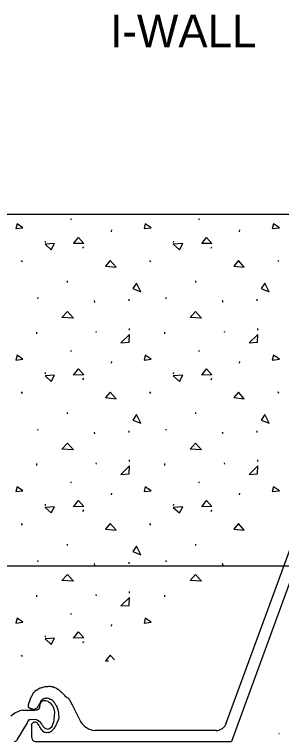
# Model space of a CAD drawing. Extents: x 22369.6 to 22384.3, y 22369.6 to 22381.8.
# Drawn here: x 22371.507 to 22371.886, y 22378.862 to 22379.896 of the extents above; entities that cross this region are included whole.
import ezdxf

# ---------------------------------------------------------------- set-up
doc = ezdxf.new("R2010")
doc.units = 0
for name, color, linetype in [('Level 1', 7, 'Continuous'), ('Level 10', 7, 'Continuous'), ('Level 4', 7, 'Continuous'), ('Level 8', 7, 'Continuous')]:
    doc.layers.add(name, color=color, linetype=linetype)

msp = doc.modelspace()

# ---------------------------------------------------------------- linework, layer by layer
at = {"layer": 'Level 1'}
for p, q in [((22371.8077, 22378.8878), (22371.9809, 22379.3614)), ((22371.9881, 22379.3356), (22371.8149, 22378.8619)), ((22370.8029, 22379.1117), (22371.5521, 22379.1117)), ((22371.5521, 22379.1117), (22372.3014, 22379.1117)), ((22371.5887, 22378.9141), (22371.6005, 22378.8901)), ((22371.5179, 22378.9064), (22371.5354, 22378.9063)), ((22371.5106, 22378.8641), (22371.5249, 22378.8885)), ((22371.5312, 22378.867), (22371.5312, 22378.8838)), ((22371.7931, 22378.8775), (22371.6207, 22378.8775)), ((22371.5358, 22378.8619), (22371.8149, 22378.8619))]:
    msp.add_line(p, q, dxfattribs=at)
for points in [[(22371.5388, 22378.9097), (22371.5384, 22378.9092), (22371.5374, 22378.9086), (22371.5371, 22378.9086), (22371.5363, 22378.9078), (22371.5356, 22378.9076), (22371.5354, 22378.9074), (22371.5342, 22378.9074), (22371.5338, 22378.9074), (22371.5332, 22378.9075), (22371.5329, 22378.9075), (22371.5323, 22378.9076), (22371.5319, 22378.9076), (22371.5316, 22378.9077), (22371.5313, 22378.9077), (22371.5306, 22378.9081), (22371.5298, 22378.9082), (22371.5294, 22378.9084), (22371.5291, 22378.9086), (22371.5288, 22378.9089), (22371.5276, 22378.9096), (22371.5272, 22378.9098), (22371.5271, 22378.9101), (22371.5267, 22378.9104), (22371.5265, 22378.9109), (22371.5264, 22378.912), (22371.5266, 22378.9132), (22371.5266, 22378.9144), (22371.5268, 22378.9149), (22371.5269, 22378.9155), (22371.5271, 22378.916), (22371.5271, 22378.9167), (22371.5282, 22378.9187), (22371.5286, 22378.9199), (22371.5286, 22378.9202), (22371.5288, 22378.9209), (22371.5289, 22378.9212), (22371.5295, 22378.9227), (22371.5299, 22378.9239), (22371.5304, 22378.9254), (22371.5307, 22378.9257), (22371.5312, 22378.9262), (22371.5319, 22378.9276), (22371.5322, 22378.9283), (22371.5326, 22378.9293), (22371.533, 22378.9301), (22371.5332, 22378.9303), (22371.5334, 22378.9308), (22371.5336, 22378.9311), (22371.5342, 22378.9316), (22371.535, 22378.9322), (22371.5352, 22378.9325), (22371.5357, 22378.9328), (22371.5359, 22378.9331), (22371.5361, 22378.9333), (22371.5366, 22378.9341), (22371.5374, 22378.9346), (22371.5382, 22378.935), (22371.5384, 22378.9353), (22371.5406, 22378.9369), (22371.542, 22378.9375), (22371.5426, 22378.9378), (22371.5433, 22378.938), (22371.5439, 22378.9382), (22371.5456, 22378.9385), (22371.5463, 22378.9386), (22371.5471, 22378.9389), (22371.5481, 22378.9394), (22371.549, 22378.9395), (22371.5501, 22378.9399), (22371.551, 22378.9399), (22371.5544, 22378.9401), (22371.5553, 22378.9404), (22371.5565, 22378.9405), (22371.5573, 22378.9404), (22371.5583, 22378.9401), (22371.5598, 22378.9401), (22371.5605, 22378.9399), (22371.5615, 22378.9393), (22371.5622, 22378.9391), (22371.563, 22378.9389), (22371.5633, 22378.9386), (22371.5655, 22378.938), (22371.566, 22378.9378), (22371.5669, 22378.9374), (22371.5683, 22378.9363)], [(22371.5683, 22378.9363), (22371.5693, 22378.9356), (22371.5701, 22378.935), (22371.5705, 22378.9344), (22371.5715, 22378.9336), (22371.5721, 22378.9329), (22371.5726, 22378.9326), (22371.5728, 22378.9325), (22371.5736, 22378.932), (22371.574, 22378.9315), (22371.5741, 22378.9312), (22371.5748, 22378.9305), (22371.5752, 22378.9299), (22371.577, 22378.9282), (22371.5771, 22378.9276), (22371.578, 22378.9271), (22371.5783, 22378.9267), (22371.5799, 22378.9253), (22371.5811, 22378.9246), (22371.5824, 22378.9239), (22371.5827, 22378.9237), (22371.5831, 22378.9232), (22371.5836, 22378.9229), (22371.5842, 22378.922), (22371.5843, 22378.9217), (22371.5844, 22378.9215), (22371.5846, 22378.9211), (22371.5846, 22378.9212), (22371.5847, 22378.9212), (22371.5887, 22378.9141)], [(22371.5249, 22378.8885), (22371.5256, 22378.8904), (22371.5254, 22378.8904), (22371.5281, 22378.8929), (22371.5294, 22378.8933), (22371.5352, 22378.8935), (22371.538, 22378.893), (22371.5415, 22378.8908), (22371.545, 22378.8871), (22371.5461, 22378.8851), (22371.5466, 22378.8846), (22371.547, 22378.8836), (22371.5493, 22378.8814), (22371.551, 22378.8803), (22371.5536, 22378.8794), (22371.5563, 22378.8802), (22371.5601, 22378.883), (22371.5612, 22378.8863), (22371.5624, 22378.8899), (22371.5632, 22378.8928), (22371.5641, 22378.9041), (22371.5639, 22378.9039), (22371.5636, 22378.9061), (22371.5629, 22378.9077), (22371.5621, 22378.9107), (22371.561, 22378.9124), (22371.5589, 22378.9154), (22371.556, 22378.9175), (22371.5545, 22378.9185), (22371.551, 22378.9197), (22371.5505, 22378.9195), (22371.5503, 22378.9198), (22371.5489, 22378.9195), (22371.548, 22378.9196), (22371.5456, 22378.9187), (22371.5448, 22378.9185), (22371.5448, 22378.9182), (22371.5435, 22378.9169), (22371.5426, 22378.9146), (22371.5424, 22378.9111), (22371.5423, 22378.9103), (22371.5411, 22378.9076), (22371.5384, 22378.9062), (22371.5383, 22378.9066), (22371.5383, 22378.9064), (22371.5354, 22378.9063)], [(22371.5693, 22378.8929), (22371.5695, 22378.8933), (22371.57, 22378.8956), (22371.57, 22378.896), (22371.57, 22378.8964), (22371.5701, 22378.8971), (22371.5701, 22378.8979), (22371.5697, 22378.8995), (22371.5696, 22378.9001), (22371.5696, 22378.9002), (22371.5697, 22378.9006), (22371.5696, 22378.9007), (22371.5697, 22378.9012), (22371.5696, 22378.9017), (22371.5698, 22378.9022), (22371.5696, 22378.9028), (22371.5691, 22378.9046), (22371.5686, 22378.9068), (22371.5684, 22378.9074), (22371.5682, 22378.9078), (22371.5681, 22378.9082), (22371.5681, 22378.9086), (22371.5679, 22378.9089), (22371.5678, 22378.9094), (22371.5677, 22378.9098), (22371.5675, 22378.9102), (22371.5674, 22378.9106), (22371.5671, 22378.9113), (22371.567, 22378.9118), (22371.5668, 22378.9124), (22371.566, 22378.9132), (22371.5655, 22378.9136), (22371.5651, 22378.9145), (22371.5641, 22378.9162), (22371.5639, 22378.9166), (22371.5637, 22378.9169), (22371.5631, 22378.9178), (22371.5625, 22378.9183), (22371.5622, 22378.9184), (22371.562, 22378.9187), (22371.5615, 22378.9192), (22371.5609, 22378.92), (22371.5604, 22378.9204), (22371.5601, 22378.9206), (22371.5599, 22378.9208), (22371.5596, 22378.9209), (22371.5594, 22378.921), (22371.559, 22378.9212), (22371.5581, 22378.9215), (22371.5575, 22378.9216), (22371.5566, 22378.9222), (22371.5551, 22378.9229), (22371.5547, 22378.923), (22371.553, 22378.9234), (22371.5523, 22378.9233), (22371.5519, 22378.9233), (22371.5513, 22378.9231), (22371.5508, 22378.923), (22371.5505, 22378.923), (22371.5496, 22378.9229), (22371.5493, 22378.9229), (22371.5485, 22378.9225), (22371.548, 22378.9224), (22371.5473, 22378.9222), (22371.5469, 22378.9218), (22371.5466, 22378.9216), (22371.5461, 22378.9214), (22371.5458, 22378.9211), (22371.5456, 22378.9207), (22371.5453, 22378.9206), (22371.5452, 22378.9204), (22371.5448, 22378.9201), (22371.5446, 22378.9199), (22371.5443, 22378.9195), (22371.5437, 22378.9182), (22371.543, 22378.9167), (22371.5427, 22378.9162), (22371.5422, 22378.9154), (22371.5419, 22378.9148), (22371.5409, 22378.9132), (22371.5402, 22378.9124), (22371.5398, 22378.9115), (22371.5397, 22378.9112), (22371.5394, 22378.9109), (22371.5392, 22378.9103), (22371.5388, 22378.9097)], [(22371.5312, 22378.8838), (22371.5314, 22378.8841), (22371.5313, 22378.8847), (22371.5312, 22378.8847), (22371.5312, 22378.8851), (22371.531, 22378.8858), (22371.5311, 22378.886), (22371.5311, 22378.8859), (22371.5311, 22378.8862), (22371.5314, 22378.8864), (22371.5315, 22378.8868), (22371.5319, 22378.8875), (22371.5319, 22378.8875), (22371.5325, 22378.8883), (22371.5327, 22378.8884), (22371.533, 22378.8888), (22371.5335, 22378.8891), (22371.5339, 22378.8893), (22371.535, 22378.8894), (22371.5361, 22378.8896), (22371.5367, 22378.8896), (22371.5373, 22378.8894), (22371.5385, 22378.889), (22371.5389, 22378.8885), (22371.5389, 22378.8879), (22371.5394, 22378.8874), (22371.5395, 22378.8869), (22371.5404, 22378.8862), (22371.5404, 22378.886), (22371.541, 22378.8848), (22371.5416, 22378.8839), (22371.5423, 22378.8831), (22371.5427, 22378.8819), (22371.5429, 22378.8816), (22371.5434, 22378.8808), (22371.5435, 22378.8806), (22371.544, 22378.8795), (22371.5442, 22378.8793), (22371.5445, 22378.8791), (22371.5448, 22378.8788), (22371.5458, 22378.8778), (22371.5459, 22378.8776), (22371.5461, 22378.8774), (22371.5464, 22378.877), (22371.5466, 22378.8766), (22371.5473, 22378.8761), (22371.5479, 22378.8759), (22371.5485, 22378.8755), (22371.5493, 22378.8753), (22371.5496, 22378.8751), (22371.5501, 22378.8751), (22371.5503, 22378.875), (22371.5517, 22378.8748), (22371.5524, 22378.8748), (22371.554, 22378.8749), (22371.5544, 22378.8748), (22371.555, 22378.8748), (22371.5564, 22378.8751), (22371.558, 22378.8758), (22371.5583, 22378.876), (22371.5586, 22378.8761), (22371.559, 22378.8764), (22371.5595, 22378.8768), (22371.5599, 22378.877), (22371.5601, 22378.8773), (22371.5608, 22378.8779), (22371.5611, 22378.8784), (22371.5629, 22378.8803), (22371.5633, 22378.8809), (22371.5639, 22378.8821), (22371.5647, 22378.8833), (22371.5649, 22378.8836), (22371.5651, 22378.884), (22371.5654, 22378.8843), (22371.5659, 22378.8852), (22371.5665, 22378.8864), (22371.5669, 22378.8872), (22371.5676, 22378.8892), (22371.5676, 22378.8894), (22371.5678, 22378.8898), (22371.5679, 22378.8901), (22371.5681, 22378.8904), (22371.5685, 22378.8918), (22371.5688, 22378.8923), (22371.5693, 22378.8929)]]:
    msp.add_lwpolyline(points, dxfattribs=at)
for centre, radius, start, end in [((22371.5292, 22378.8642), 0.0437, 104.9327, 129.732), ((22371.6235, 22378.9044), 0.027, 211.905, 264.1589), ((22371.7931, 22378.8931), 0.0156, 270, 339.9138), ((22371.5063, 22378.8671), 0.00523, 275.0736, 325.5224), ((22371.5365, 22378.8671), 0.00521, 180.2909, 270.0528)]:
    msp.add_arc(centre, radius, start, end, dxfattribs=at)
at = {"layer": 'Level 10'}
msp.add_line((22372.2493, 22379.6114), (22371.2877, 22379.6114), dxfattribs=at)
at = {"layer": 'Level 8'}
for p, q in [((22371.5866, 22379.6036), (22371.5875, 22379.6055)), ((22371.7688, 22379.6036), (22371.7697, 22379.6055)), ((22371.6444, 22379.5868), (22371.6448, 22379.5892)), ((22371.8266, 22379.5868), (22371.827, 22379.5892)), ((22371.5506, 22379.5716), (22371.5507, 22379.5734)), ((22371.6038, 22379.5632), (22371.605, 22379.5653)), ((22371.7328, 22379.5716), (22371.733, 22379.5734)), ((22371.786, 22379.5632), (22371.7872, 22379.5653)), ((22371.518, 22379.5437), (22371.5168, 22379.5459)), ((22371.7002, 22379.5437), (22371.699, 22379.5459)), ((22371.8824, 22379.5437), (22371.8812, 22379.5459)), ((22371.5821, 22379.5147), (22371.582, 22379.5167)), ((22371.7643, 22379.5147), (22371.7642, 22379.5167)), ((22371.5397, 22379.4913), (22371.5401, 22379.4932)), ((22371.722, 22379.4913), (22371.7223, 22379.4932)), ((22371.6209, 22379.4863), (22371.6202, 22379.4888)), ((22371.6694, 22379.4883), (22371.6694, 22379.4908)), ((22371.8031, 22379.4863), (22371.8024, 22379.4888)), ((22371.8516, 22379.4883), (22371.8516, 22379.4908)), ((22371.5382, 22379.4415), (22371.5382, 22379.444)), ((22371.6234, 22379.4432), (22371.6227, 22379.445)), ((22371.6703, 22379.4469), (22371.6703, 22379.4492)), ((22371.7204, 22379.4415), (22371.7204, 22379.444)), ((22371.8056, 22379.4432), (22371.8049, 22379.445)), ((22371.8525, 22379.4469), (22371.8525, 22379.4492)), ((22371.5866, 22379.4165), (22371.5875, 22379.4185)), ((22371.7688, 22379.4165), (22371.7697, 22379.4185)), ((22371.6444, 22379.3997), (22371.6448, 22379.4021)), ((22371.8266, 22379.3997), (22371.827, 22379.4021)), ((22371.5506, 22379.3845), (22371.5507, 22379.3863)), ((22371.7328, 22379.3845), (22371.733, 22379.3863)), ((22371.6038, 22379.3762), (22371.605, 22379.3783)), ((22371.786, 22379.3762), (22371.7872, 22379.3783)), ((22371.518, 22379.3567), (22371.5168, 22379.3589)), ((22371.7002, 22379.3567), (22371.699, 22379.3589)), ((22371.8824, 22379.3567), (22371.8812, 22379.3589)), ((22371.5821, 22379.3276), (22371.582, 22379.3297)), ((22371.7643, 22379.3276), (22371.7642, 22379.3297)), ((22371.5397, 22379.3043), (22371.5401, 22379.3061)), ((22371.6209, 22379.2993), (22371.6202, 22379.3018)), ((22371.6694, 22379.3013), (22371.6694, 22379.3038)), ((22371.722, 22379.3043), (22371.7223, 22379.3061)), ((22371.8031, 22379.2993), (22371.8024, 22379.3018)), ((22371.8516, 22379.3013), (22371.8516, 22379.3038)), ((22371.5382, 22379.2545), (22371.5382, 22379.257)), ((22371.6234, 22379.2562), (22371.6227, 22379.258)), ((22371.6703, 22379.2598), (22371.6703, 22379.2622)), ((22371.7204, 22379.2545), (22371.7204, 22379.257)), ((22371.8056, 22379.2562), (22371.8049, 22379.258)), ((22371.8525, 22379.2598), (22371.8525, 22379.2622)), ((22371.5866, 22379.2295), (22371.5875, 22379.2314)), ((22371.7688, 22379.2295), (22371.7697, 22379.2314)), ((22371.6444, 22379.2127), (22371.6448, 22379.2151)), ((22371.8266, 22379.2127), (22371.827, 22379.2151)), ((22371.5506, 22379.1975), (22371.5507, 22379.1993)), ((22371.7328, 22379.1975), (22371.733, 22379.1993)), ((22371.6038, 22379.1891), (22371.605, 22379.1912)), ((22371.786, 22379.1891), (22371.7872, 22379.1912)), ((22371.518, 22379.1696), (22371.5168, 22379.1718)), ((22371.7002, 22379.1696), (22371.699, 22379.1718)), ((22371.5821, 22379.1406), (22371.582, 22379.1426)), ((22371.7643, 22379.1406), (22371.7642, 22379.1426)), ((22371.5397, 22379.1172), (22371.5401, 22379.1191)), ((22371.6209, 22379.1123), (22371.6202, 22379.1148)), ((22371.6694, 22379.1143), (22371.6694, 22379.1168)), ((22371.722, 22379.1172), (22371.7223, 22379.1191)), ((22371.8031, 22379.1123), (22371.8024, 22379.1148)), ((22371.5382, 22379.0674), (22371.5382, 22379.0699)), ((22371.6234, 22379.0691), (22371.6227, 22379.0709)), ((22371.6703, 22379.0728), (22371.6703, 22379.0751)), ((22371.7204, 22379.0674), (22371.7204, 22379.0699)), ((22371.5866, 22379.0424), (22371.5875, 22379.0444)), ((22371.6444, 22379.0256), (22371.6448, 22379.0281)), ((22371.5506, 22379.0104), (22371.5507, 22379.0123)), ((22371.6038, 22379.0021), (22371.605, 22379.0042)), ((22371.518, 22378.9826), (22371.5168, 22378.9848))]:
    msp.add_line(p, q, dxfattribs=at)
for points in [[(22371.5086, 22379.5911), (22371.5187, 22379.5924), (22371.5102, 22379.5981)], [(22371.6908, 22379.5911), (22371.7009, 22379.5924), (22371.6924, 22379.5981)], [(22371.873, 22379.5911), (22371.8831, 22379.5924), (22371.8746, 22379.5981)], [(22371.5907, 22379.5698), (22371.5974, 22379.5787), (22371.605, 22379.5701)], [(22371.7729, 22379.5698), (22371.7796, 22379.5787), (22371.7872, 22379.5701)], [(22371.55, 22379.5688), (22371.5588, 22379.5609), (22371.5636, 22379.5698)], [(22371.7322, 22379.5688), (22371.741, 22379.5609), (22371.7458, 22379.5698)], [(22371.651, 22379.5362), (22371.6428, 22379.5457), (22371.6362, 22379.5378)], [(22371.8332, 22379.5362), (22371.825, 22379.5457), (22371.8184, 22379.5378)], [(22371.6748, 22379.5058), (22371.6862, 22379.5014), (22371.6802, 22379.5137)], [(22371.857, 22379.5058), (22371.8684, 22379.5014), (22371.8624, 22379.5137)], [(22371.574, 22379.4646), (22371.5819, 22379.4732), (22371.5904, 22379.4637)], [(22371.7562, 22379.4646), (22371.7641, 22379.4732), (22371.7726, 22379.4637)], [(22371.6697, 22379.4295), (22371.6703, 22379.4406), (22371.658, 22379.4286)], [(22371.8519, 22379.4295), (22371.8525, 22379.4406), (22371.8402, 22379.4286)], [(22371.5086, 22379.4041), (22371.5187, 22379.4054), (22371.5102, 22379.4111)], [(22371.6908, 22379.4041), (22371.7009, 22379.4054), (22371.6924, 22379.4111)], [(22371.873, 22379.4041), (22371.8831, 22379.4054), (22371.8746, 22379.4111)], [(22371.5907, 22379.3828), (22371.5974, 22379.3916), (22371.605, 22379.3831)], [(22371.7729, 22379.3828), (22371.7796, 22379.3916), (22371.7872, 22379.3831)], [(22371.55, 22379.3818), (22371.5588, 22379.3739), (22371.5636, 22379.3828)], [(22371.7322, 22379.3818), (22371.741, 22379.3739), (22371.7458, 22379.3828)], [(22371.651, 22379.3492), (22371.6428, 22379.3587), (22371.6362, 22379.3508)], [(22371.8332, 22379.3492), (22371.825, 22379.3587), (22371.8184, 22379.3508)], [(22371.6748, 22379.3188), (22371.6862, 22379.3144), (22371.6802, 22379.3267)], [(22371.857, 22379.3188), (22371.8684, 22379.3144), (22371.8624, 22379.3267)], [(22371.574, 22379.2776), (22371.5819, 22379.2862), (22371.5904, 22379.2767)], [(22371.7562, 22379.2776), (22371.7641, 22379.2862), (22371.7726, 22379.2767)], [(22371.6697, 22379.2425), (22371.6703, 22379.2536), (22371.658, 22379.2416)], [(22371.8519, 22379.2425), (22371.8525, 22379.2536), (22371.8402, 22379.2416)], [(22371.5086, 22379.2171), (22371.5187, 22379.2183), (22371.5102, 22379.2241)], [(22371.6908, 22379.2171), (22371.7009, 22379.2183), (22371.6924, 22379.2241)], [(22371.873, 22379.2171), (22371.8831, 22379.2183), (22371.8746, 22379.2241)], [(22371.5907, 22379.1957), (22371.5974, 22379.2046), (22371.605, 22379.1961)], [(22371.7729, 22379.1957), (22371.7796, 22379.2046), (22371.7872, 22379.1961)], [(22371.55, 22379.1948), (22371.5588, 22379.1868), (22371.5636, 22379.1957)], [(22371.7322, 22379.1948), (22371.741, 22379.1868), (22371.7458, 22379.1957)], [(22371.651, 22379.1621), (22371.6428, 22379.1716), (22371.6362, 22379.1638)], [(22371.8332, 22379.1621), (22371.825, 22379.1716), (22371.8184, 22379.1638)], [(22371.6748, 22379.1318), (22371.6862, 22379.1273), (22371.6802, 22379.1396)], [(22371.574, 22379.0906), (22371.5819, 22379.0991), (22371.5904, 22379.0896)], [(22371.7562, 22379.0906), (22371.7641, 22379.0991), (22371.7726, 22379.0896)], [(22371.6697, 22379.0554), (22371.6703, 22379.0666), (22371.658, 22379.0545)], [(22371.5086, 22379.03), (22371.5187, 22379.0313), (22371.5102, 22379.037)], [(22371.6908, 22379.03), (22371.7009, 22379.0313), (22371.6924, 22379.037)], [(22371.5907, 22379.0087), (22371.5974, 22379.0176), (22371.605, 22379.009)], [(22371.55, 22379.0077), (22371.5588, 22378.9998), (22371.5636, 22379.0087)]]:
    msp.add_lwpolyline(points, close=True, dxfattribs=at)
for points in [[(22371.6428, 22378.9846), (22371.6362, 22378.9767)], [(22371.6362, 22378.9767), (22371.6401, 22378.9763)], [(22371.6487, 22378.9778), (22371.6428, 22378.9846)], [(22371.8823, 22378.8731), (22371.883, 22378.8732)], [(22371.883, 22378.8732), (22371.8825, 22378.8736)]]:
    msp.add_lwpolyline(points, dxfattribs=at)

# ---------------------------------------------------------------- texts
at = {"layer": 'Level 4'}
msp.add_text('I-WALL', height=0.04663, dxfattribs=at).set_placement((22371.6426, 22379.8489))

doc.saveas('drawing.dxf')
